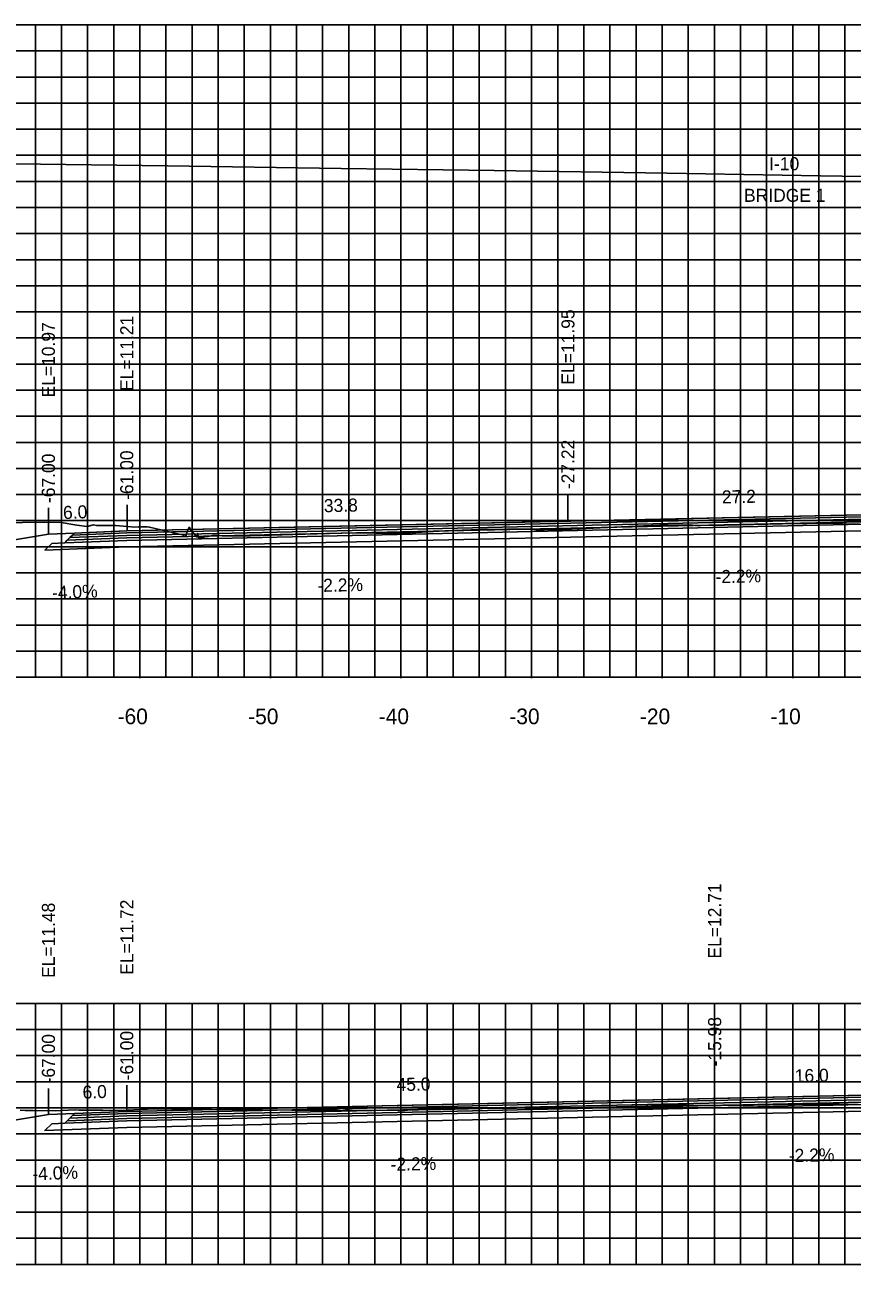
# Model space of a CAD drawing. Extents: x 1797419 to 1809236, y 248759 to 251512.
# Drawn here: x 1802902.2 to 1802965.6, y 250099.4 to 250194.4 of the extents above; entities that cross this region are included whole.
import ezdxf

# ---------------------------------------------------------------- set-up
doc = ezdxf.new("R2010")
doc.units = 0
for name, color, linetype in [('10', 7, 'Continuous'), ('3', 7, 'Continuous'), ('4', 7, 'Continuous'), ('60', 7, 'Continuous'), ('BASE', 7, 'Continuous'), ('CL-CNST', 7, 'Continuous'), ('Level 62', 7, 'Continuous'), ('LOWER BINDER', 7, 'Continuous'), ('M-ROADS', 7, 'Continuous'), ('UPPER BINDER', 7, 'Continuous'), ('WEARING', 7, 'Continuous')]:
    doc.layers.add(name, color=color, linetype=linetype)

msp = doc.modelspace()

# ---------------------------------------------------------------- linework, layer by layer
for p, q in [((1802943.786, 250156.385), (1802943.786, 250158.385)), ((1802903.998, 250155.401), (1802903.998, 250157.401)), ((1802904.002, 250155.402), (1802904.002, 250157.402)), ((1802910.031, 250155.643), (1802910.031, 250157.643)), ((1802955.024, 250112.146), (1802955.024, 250114.146)), ((1802904.002, 250110.916), (1802904.002, 250112.916)), ((1802910.002, 250111.156), (1802910.002, 250113.156))]:
    msp.add_line(p, q)
at = {"layer": '60'}
for p, q in [((1802821.002, 250144.432), (1803121.002, 250144.432)), ((1802911.002, 250144.372), (1802911.002, 250144.432)), ((1802921.002, 250144.372), (1802921.002, 250144.432)), ((1802931.002, 250144.372), (1802931.002, 250144.432)), ((1802941.002, 250144.372), (1802941.002, 250144.432)), ((1802951.002, 250144.372), (1802951.002, 250144.432)), ((1802961.002, 250144.372), (1802961.002, 250144.432)), ((1802821.002, 250099.432), (1803121.002, 250099.432)), ((1802911.002, 250099.372), (1802911.002, 250099.432)), ((1802921.002, 250099.372), (1802921.002, 250099.432)), ((1802931.002, 250099.372), (1802931.002, 250099.432)), ((1802941.002, 250099.372), (1802941.002, 250099.432)), ((1802951.002, 250099.372), (1802951.002, 250099.432)), ((1802961.002, 250099.372), (1802961.002, 250099.432))]:
    msp.add_line(p, q, dxfattribs=at)
at = {"layer": 'BASE'}
for points in [[(1802904.251, 250154.692), (1802905.251, 250154.732), (1802910.002, 250154.922), (1802971.001, 250156.264), (1803023.675, 250157.356), (1803028.423, 250157.166), (1803029.423, 250157.126), (1803029.943, 250156.606), (1803023.675, 250156.856), (1802971.001, 250155.764), (1802910.002, 250154.422), (1802903.731, 250154.171)], [(1802904.252, 250110.206), (1802905.252, 250110.246), (1802910.002, 250110.436), (1802971.002, 250111.778), (1803042.759, 250112.029), (1803047.507, 250111.839), (1803048.507, 250111.799), (1803049.028, 250111.278), (1803042.759, 250111.529), (1802971.002, 250111.278), (1802910.002, 250109.936), (1802903.73, 250109.685)]]:
    msp.add_lwpolyline(points, close=True, dxfattribs=at)
at = {"layer": 'CL-CNST'}
for points in [[(1802821.002, 250184.731), (1802826.544, 250184.674), (1802838.126, 250184.556), (1802851.511, 250184.405), (1802863.126, 250184.273), (1802876.158, 250184.112), (1802887.526, 250183.971), (1802887.846, 250183.967), (1802888.126, 250183.963), (1802901.445, 250183.783), (1802913.126, 250183.625), (1802926.412, 250183.43), (1802938.126, 250183.258), (1802951.38, 250183.05), (1802963.126, 250182.864), (1802976.347, 250182.641), (1802988.126, 250182.443), (1803001.314, 250182.205), (1803013.126, 250181.993), (1803021.409, 250181.836), (1803028.86, 250181.696), (1803033.732, 250181.601)], [(1802859.005, 250156.901), (1802859.014, 250156.899), (1802879.001, 250151.902), (1802883.002, 250151.902), (1802883.006, 250151.903), (1802890.197, 250153.101), (1802904.002, 250155.402), (1802906.002, 250155.482), (1802908.802, 250155.594), (1802910.002, 250155.642), (1802910.016, 250155.642), (1802943.786, 250156.385), (1802971.001, 250156.984), (1803023.673, 250158.076), (1803025.913, 250157.986), (1803027.673, 250157.916), (1803029.673, 250157.836), (1803029.677, 250157.835), (1803038.777, 250156.319)], [(1802862.07, 250111.649), (1802862.074, 250111.648), (1802875.767, 250108.225), (1802879.002, 250107.416), (1802883.002, 250107.416), (1802904.002, 250110.916), (1802906.001, 250110.996), (1802910.002, 250111.156), (1802955.024, 250112.146), (1802971, 250112.498), (1802971.002, 250112.498), (1802990.3, 250112.565), (1803042.758, 250112.749), (1803044.918, 250112.663), (1803046.757, 250112.589), (1803048.758, 250112.509), (1803055.302, 250111.418), (1803069.757, 250109.009), (1803069.76, 250109.009), (1803071.671, 250109.009), (1803073.757, 250109.668), (1803075.3, 250109.922), (1803081.479, 250110.939)]]:
    msp.add_lwpolyline(points, dxfattribs=at)
at = {"layer": 'Level 62'}
for p, q in [((1802821.002, 250194.432), (1803121.002, 250194.432)), ((1802903.002, 250144.432), (1802903.002, 250194.432)), ((1802905.002, 250144.432), (1802905.002, 250194.432)), ((1802907.002, 250144.432), (1802907.002, 250194.432)), ((1802909.002, 250144.432), (1802909.002, 250194.432)), ((1802911.002, 250144.432), (1802911.002, 250194.432)), ((1802913.002, 250144.432), (1802913.002, 250194.432)), ((1802915.002, 250144.432), (1802915.002, 250194.432)), ((1802917.002, 250144.432), (1802917.002, 250194.432)), ((1802919.002, 250144.432), (1802919.002, 250194.432)), ((1802921.002, 250144.432), (1802921.002, 250194.432)), ((1802923.002, 250144.432), (1802923.002, 250194.432)), ((1802925.002, 250144.432), (1802925.002, 250194.432)), ((1802927.002, 250144.432), (1802927.002, 250194.432)), ((1802929.002, 250144.432), (1802929.002, 250194.432)), ((1802931.002, 250144.432), (1802931.002, 250194.432)), ((1802933.002, 250144.432), (1802933.002, 250194.432)), ((1802935.002, 250144.432), (1802935.002, 250194.432)), ((1802937.002, 250144.432), (1802937.002, 250194.432)), ((1802939.002, 250144.432), (1802939.002, 250194.432)), ((1802941.002, 250144.432), (1802941.002, 250194.432)), ((1802943.002, 250144.432), (1802943.002, 250194.432)), ((1802945.002, 250144.432), (1802945.002, 250194.432)), ((1802947.002, 250144.432), (1802947.002, 250194.432)), ((1802949.002, 250144.432), (1802949.002, 250194.432)), ((1802951.002, 250144.432), (1802951.002, 250194.432)), ((1802953.002, 250144.432), (1802953.002, 250194.432)), ((1802955.002, 250144.432), (1802955.002, 250194.432)), ((1802957.002, 250144.432), (1802957.002, 250194.432)), ((1802959.002, 250144.432), (1802959.002, 250194.432)), ((1802961.002, 250144.432), (1802961.002, 250194.432)), ((1802963.002, 250144.432), (1802963.002, 250194.432)), ((1802965.002, 250144.432), (1802965.002, 250194.432)), ((1802821.002, 250192.432), (1803121.002, 250192.432)), ((1802821.002, 250190.432), (1803121.002, 250190.432)), ((1802821.002, 250188.432), (1803121.002, 250188.432)), ((1802821.002, 250186.432), (1803121.002, 250186.432)), ((1802821.002, 250184.432), (1803121.002, 250184.432)), ((1802821.002, 250182.432), (1803121.002, 250182.432)), ((1802821.002, 250180.432), (1803121.002, 250180.432)), ((1802821.002, 250178.432), (1803121.002, 250178.432)), ((1802821.002, 250176.432), (1803121.002, 250176.432)), ((1802821.002, 250174.432), (1803121.002, 250174.432)), ((1802821.002, 250172.432), (1803121.002, 250172.432)), ((1802821.002, 250170.432), (1803121.002, 250170.432)), ((1802821.002, 250168.432), (1803121.002, 250168.432)), ((1802821.002, 250166.432), (1803121.002, 250166.432)), ((1802821.002, 250164.432), (1803121.002, 250164.432)), ((1802821.002, 250162.432), (1803121.002, 250162.432)), ((1802821.002, 250160.432), (1803121.002, 250160.432)), ((1802821.002, 250158.432), (1803121.002, 250158.432)), ((1802821.002, 250156.432), (1803121.002, 250156.432)), ((1802821.002, 250154.432), (1803121.002, 250154.432)), ((1802821.002, 250152.432), (1803121.002, 250152.432)), ((1802821.002, 250150.432), (1803121.002, 250150.432)), ((1802821.002, 250148.432), (1803121.002, 250148.432)), ((1802821.002, 250146.432), (1803121.002, 250146.432)), ((1802821.002, 250144.432), (1803121.002, 250144.432)), ((1802821.002, 250119.432), (1803121.002, 250119.432)), ((1802903.002, 250099.432), (1802903.002, 250119.432)), ((1802905.002, 250099.432), (1802905.002, 250119.432)), ((1802907.002, 250099.432), (1802907.002, 250119.432)), ((1802909.002, 250099.432), (1802909.002, 250119.432)), ((1802911.002, 250099.432), (1802911.002, 250119.432)), ((1802913.002, 250099.432), (1802913.002, 250119.432)), ((1802915.002, 250099.432), (1802915.002, 250119.432)), ((1802917.002, 250099.432), (1802917.002, 250119.432)), ((1802919.002, 250099.432), (1802919.002, 250119.432)), ((1802921.002, 250099.432), (1802921.002, 250119.432)), ((1802923.002, 250099.432), (1802923.002, 250119.432)), ((1802925.002, 250099.432), (1802925.002, 250119.432)), ((1802927.002, 250099.432), (1802927.002, 250119.432)), ((1802929.002, 250099.432), (1802929.002, 250119.432)), ((1802931.002, 250099.432), (1802931.002, 250119.432)), ((1802933.002, 250099.432), (1802933.002, 250119.432)), ((1802935.002, 250099.432), (1802935.002, 250119.432)), ((1802937.002, 250099.432), (1802937.002, 250119.432)), ((1802939.002, 250099.432), (1802939.002, 250119.432)), ((1802941.002, 250099.432), (1802941.002, 250119.432)), ((1802943.002, 250099.432), (1802943.002, 250119.432)), ((1802945.002, 250099.432), (1802945.002, 250119.432)), ((1802947.002, 250099.432), (1802947.002, 250119.432)), ((1802949.002, 250099.432), (1802949.002, 250119.432)), ((1802951.002, 250099.432), (1802951.002, 250119.432)), ((1802953.002, 250099.432), (1802953.002, 250119.432)), ((1802955.002, 250099.432), (1802955.002, 250119.432)), ((1802957.002, 250099.432), (1802957.002, 250119.432)), ((1802959.002, 250099.432), (1802959.002, 250119.432)), ((1802961.002, 250099.432), (1802961.002, 250119.432)), ((1802963.002, 250099.432), (1802963.002, 250119.432)), ((1802965.002, 250099.432), (1802965.002, 250119.432)), ((1802821.002, 250117.432), (1803121.002, 250117.432)), ((1802821.002, 250115.432), (1803121.002, 250115.432)), ((1802821.002, 250113.432), (1803121.002, 250113.432)), ((1802821.002, 250111.432), (1803121.002, 250111.432)), ((1802821.002, 250109.432), (1803121.002, 250109.432)), ((1802821.002, 250107.432), (1803121.002, 250107.432)), ((1802821.002, 250105.432), (1803121.002, 250105.432)), ((1802821.002, 250103.432), (1803121.002, 250103.432)), ((1802821.002, 250101.432), (1803121.002, 250101.432)), ((1802821.002, 250099.432), (1803121.002, 250099.432))]:
    msp.add_line(p, q, dxfattribs=at)
at = {"layer": 'LOWER BINDER'}
for points in [[(1802910.002, 250155.112), (1802971.001, 250156.454), (1803023.675, 250157.546), (1803028.225, 250157.364), (1803028.423, 250157.166), (1803023.675, 250157.356), (1802971.001, 250156.264), (1802910.002, 250154.922), (1802905.251, 250154.732), (1802905.449, 250154.93)], [(1802910.002, 250155.302), (1802971.001, 250156.644), (1803023.673, 250157.736), (1803028.027, 250157.562), (1803028.225, 250157.364), (1803023.675, 250157.546), (1802971.001, 250156.454), (1802910.002, 250155.112), (1802905.449, 250154.93), (1802905.647, 250155.128)], [(1802910.002, 250110.816), (1802971.002, 250112.158), (1803042.758, 250112.409), (1803047.112, 250112.234), (1803047.309, 250112.037), (1803042.759, 250112.219), (1802971.002, 250111.968), (1802910.002, 250110.626), (1802905.45, 250110.444), (1802905.648, 250110.642)], [(1802910.002, 250110.626), (1802971.002, 250111.968), (1803042.759, 250112.219), (1803047.309, 250112.037), (1803047.507, 250111.839), (1803042.759, 250112.029), (1802971.002, 250111.778), (1802910.002, 250110.436), (1802905.252, 250110.246), (1802905.45, 250110.444)]]:
    msp.add_lwpolyline(points, close=True, dxfattribs=at)
at = {"layer": 'M-ROADS'}
for points in [[(1802895.311, 250156.193), (1802903.708, 250156.324), (1802904.977, 250156.296), (1802906.177, 250156.091), (1802906.96, 250155.991), (1802907.463, 250156.099), (1802907.685, 250156.052), (1802908.685, 250156.052), (1802909.159, 250156.072), (1802910.621, 250155.937), (1802910.892, 250155.957), (1802910.947, 250155.922), (1802911.142, 250155.959), (1802911.565, 250155.96), (1802911.745, 250155.943), (1802914.335, 250155.31), (1802914.475, 250155.37), (1802914.536, 250155.254), (1802914.552, 250155.318), (1802914.598, 250155.527), (1802914.604, 250155.511), (1802914.638, 250155.616), (1802914.657, 250155.627), (1802914.673, 250155.721), (1802914.682, 250155.722), (1802914.697, 250155.75), (1802914.716, 250155.793), (1802914.722, 250155.814), (1802914.767, 250155.914), (1802914.771, 250155.902), (1802914.811, 250155.91), (1802914.852, 250155.795), (1802914.914, 250155.713), (1802914.943, 250155.712), (1802915.376, 250155.171), (1802915.435, 250155.453), (1802915.461, 250155.196), (1802915.477, 250155.143), (1802915.49, 250155.13), (1802915.517, 250155.134), (1802915.532, 250155.137), (1802915.627, 250155.131), (1802915.787, 250155.121), (1802915.967, 250155.199), (1802916.241, 250155.226), (1802916.667, 250155.307), (1802916.826, 250155.295), (1802917.137, 250155.298), (1802917.28, 250155.278), (1802917.945, 250155.276), (1802919.489, 250155.258), (1802922.71, 250155.359), (1802926.479, 250155.472), (1802928.366, 250155.499), (1802928.626, 250155.5), (1802928.687, 250155.497), (1802929.11, 250155.468), (1802930.888, 250155.469), (1802931.428, 250155.472), (1802932.137, 250155.515), (1802934.353, 250155.664), (1802937.695, 250155.776), (1802938.6, 250155.746), (1802939.101, 250155.77), (1802939.765, 250155.786), (1802939.988, 250155.777), (1802940.886, 250155.768), (1802941.225, 250155.749), (1802941.36, 250155.738), (1802941.429, 250155.733), (1802941.959, 250155.739), (1802943.547, 250155.753), (1802948.976, 250156.001), (1802950.823, 250156.082), (1802951.366, 250156.092), (1802953.141, 250156.099), (1802953.542, 250156.063), (1802953.62, 250156.055), (1802953.966, 250156.056), (1802955.773, 250156.082), (1802961.321, 250156.207), (1802962.002, 250156.224), (1802962.079, 250156.216), (1802962.234, 250156.23), (1802964.366, 250156.245), (1802964.8, 250156.194), (1802964.845, 250156.189), (1802966.124, 250156.172)], [(1802901.83, 250111.252), (1802902.217, 250111.236), (1802902.686, 250111.222), (1802902.814, 250111.224), (1802902.828, 250111.224), (1802902.842, 250111.224), (1802904.578, 250111.213), (1802906.019, 250111.27), (1802906.351, 250111.264), (1802907.706, 250111.249), (1802908.16, 250111.249), (1802909.684, 250111.237), (1802910.976, 250111.314), (1802912.23, 250111.363), (1802913.431, 250111.324), (1802925.679, 250111.223), (1802926.29, 250111.223), (1802926.43, 250111.214), (1802926.77, 250111.26), (1802926.966, 250111.264), (1802928.817, 250111.228), (1802929.007, 250111.236), (1802929.428, 250111.242), (1802930.779, 250111.215), (1802931.303, 250111.217), (1802931.721, 250111.268), (1802932.337, 250111.289), (1802934.048, 250111.315), (1802938.323, 250111.395), (1802939.858, 250111.411), (1802940.432, 250111.42), (1802940.508, 250111.414), (1802940.655, 250111.407), (1802940.989, 250111.391), (1802941.161, 250111.376), (1802942.461, 250111.397), (1802943.27, 250111.405), (1802945.225, 250111.456), (1802949.772, 250111.559), (1802950.577, 250111.6), (1802952.071, 250111.643), (1802952.685, 250111.657), (1802952.866, 250111.637), (1802953.115, 250111.608), (1802954.863, 250111.622), (1802955.294, 250111.614), (1802955.526, 250111.623), (1802955.652, 250111.626), (1802955.755, 250111.627), (1802957.992, 250111.641), (1802959.268, 250111.668), (1802961.137, 250111.697), (1802961.731, 250111.711), (1802963.156, 250111.705), (1802963.615, 250111.741), (1802963.708, 250111.736), (1802963.736, 250111.742), (1802963.856, 250111.734), (1802965.304, 250111.695), (1802966.005, 250111.677)]]:
    msp.add_lwpolyline(points, dxfattribs=at)
at = {"layer": 'UPPER BINDER'}
for points in [[(1803023.673, 250157.736), (1803028.027, 250157.562), (1803027.829, 250157.76), (1803023.673, 250157.926), (1802971.001, 250156.834), (1802910.002, 250155.492), (1802905.845, 250155.326), (1802905.647, 250155.128), (1802910.002, 250155.302), (1802971.001, 250156.644)], [(1803042.758, 250112.409), (1803047.112, 250112.234), (1803046.914, 250112.432), (1803042.758, 250112.599), (1802971.002, 250112.348), (1802910.002, 250111.006), (1802905.846, 250110.84), (1802905.648, 250110.642), (1802910.002, 250110.816), (1802971.002, 250112.158)]]:
    msp.add_lwpolyline(points, close=True, dxfattribs=at)
at = {"layer": 'WEARING'}
for points in [[(1803023.673, 250157.926), (1803027.829, 250157.76), (1803027.673, 250157.916), (1803023.673, 250158.076), (1802971.001, 250156.984), (1802910.002, 250155.642), (1802906.002, 250155.482), (1802905.845, 250155.326), (1802910.002, 250155.492), (1802971.001, 250156.834)], [(1803042.758, 250112.599), (1803046.914, 250112.432), (1803046.757, 250112.589), (1803042.758, 250112.749), (1802971.002, 250112.498), (1802910.002, 250111.156), (1802906.001, 250110.996), (1802905.846, 250110.84), (1802910.002, 250111.006), (1802971.002, 250112.348)]]:
    msp.add_lwpolyline(points, close=True, dxfattribs=at)

# ---------------------------------------------------------------- texts
at = {"layer": '10'}
for s, p in [('-60', (1802909.298, 250140.832)), ('-50', (1802919.298, 250140.832)), ('-40', (1802929.298, 250140.832)), ('-30', (1802939.298, 250140.832)), ('-20', (1802949.298, 250140.832)), ('-10', (1802959.298, 250140.832))]:
    msp.add_text(s, height=1.2, dxfattribs=at).set_placement(p)
at = {"layer": '3'}
for s, p in [('I-10 ', (1802959.198, 250183.286)), ('BRIDGE 1', (1802957.272, 250180.865))]:
    msp.add_text(s, height=1, dxfattribs=at).set_placement(p)
for s, p in [('EL=11.95', (1802944.286, 250166.858)), ('EL=10.97', (1802904.498, 250165.874)), ('EL=11.21', (1802910.502, 250166.366)), ('-27.22', (1802944.286, 250158.842)), ('-67.00', (1802904.498, 250157.779)), ('-67.00', (1802904.502, 250157.78)), ('-61.00', (1802910.502, 250158.02)), ('EL=12.71', (1802955.524, 250122.871)), ('EL=11.48', (1802904.502, 250121.388)), ('EL=11.72', (1802910.502, 250121.628)), ('-15.98', (1802955.524, 250114.603)), ('-61.00', (1802910.502, 250113.534)), ('-67.00', (1802904.502, 250113.294))]:
    msp.add_text(s, height=1, rotation=90, dxfattribs=at).set_placement(p)
at = {"layer": '4'}
for s, rotation, p in [('33.8', 1.26031, (1802925.105, 250157.075)), ('27.2', 1.26031, (1802955.589, 250157.745)), ('6.0', 2.29047, (1802905.14, 250156.548)), ('-2.2%', 1.26031, (1802955.094, 250151.633)), ('-4.0%', 2.29047, (1802904.299, 250150.41)), ('-2.2%', 1.26031, (1802924.61, 250150.962)), ('16.0', 1.2603, (1802961.169, 250113.382)), ('45.0', 1.26031, (1802930.67, 250112.711)), ('6.0', 2.29031, (1802906.636, 250112.122)), ('-2.2%', 1.26031, (1802930.214, 250106.599)), ('-2.2%', 1.2603, (1802960.713, 250107.27)), ('-4.0%', 2.29144, (1802902.794, 250105.864))]:
    msp.add_text(s, height=1, rotation=rotation, dxfattribs=at).set_placement(p)

doc.saveas('drawing.dxf')
